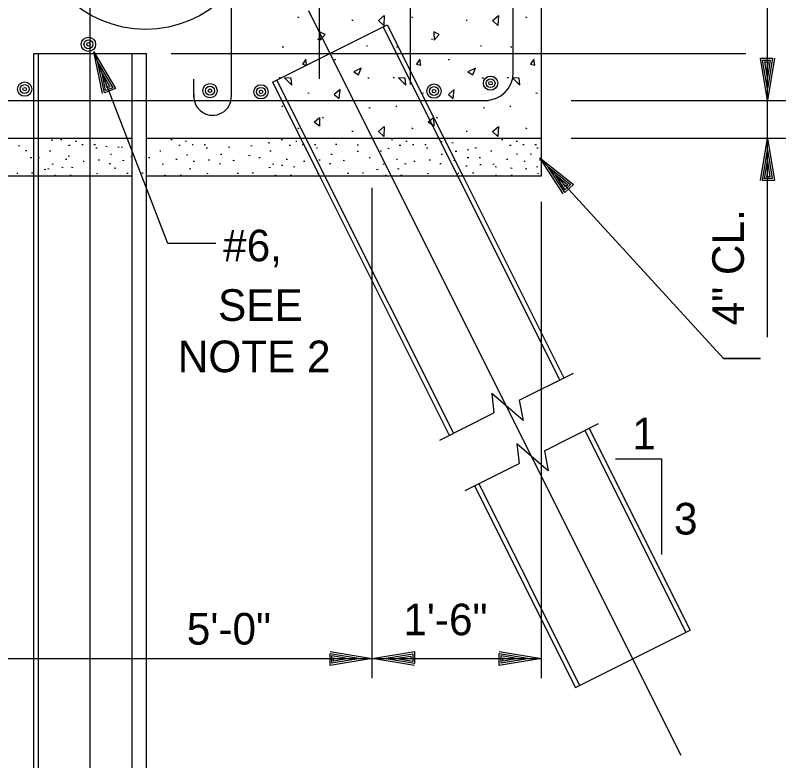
# Model space of a CAD drawing. Extents: x -11983 to -11903, y -13969.5 to -13913.5.
# Drawn here: x -11916.98 to -11910.22, y -13934.76 to -13928.16 of the extents above; entities that cross this region are included whole.
import ezdxf

# ---------------------------------------------------------------- set-up
doc = ezdxf.new("R2010")
doc.units = 0
for name, color, linetype in [('Level 2', 7, 'Continuous'), ('Level 22', 7, 'Continuous'), ('Level 3', 7, 'Continuous'), ('Level 44', 7, 'Continuous'), ('Level 6', 7, 'Continuous')]:
    doc.layers.add(name, color=color, linetype=linetype)

msp = doc.modelspace()

# ---------------------------------------------------------------- linework, layer by layer
at = {"layer": 'Level 2'}
for p, q in [((-11912.3187, -13929.5829), (-11912.3187, -13926.7524)), ((-11914.6994, -13928.7546), (-11913.684, -13928.2466)), ((-11913.7212, -13928.2654), (-11913.0627, -13929.5829)), ((-11913.684, -13928.2466), (-11913.0161, -13929.5829)), ((-11916.8142, -13928.5006), (-11915.8152, -13928.5006)), ((-11916.8142, -13929.5829), (-11916.8142, -13928.5006)), ((-11916.7727, -13936.0221), (-11916.7727, -13928.5006)), ((-11915.944, -13935.9786), (-11915.944, -13928.5006)), ((-11915.8152, -13936.0221), (-11915.8152, -13928.5006)), ((-11914.6994, -13928.7546), (-11914.2855, -13929.5829)), ((-11914.6623, -13928.7358), (-11914.2389, -13929.5829)), ((-11919.811, -13928.9169), (-11913.3132, -13928.9169)), ((-11913.3132, -13928.9169), (-11912.7877, -13928.9169)), ((-11920.3107, -13929.2499), (-11915.944, -13929.2499)), ((-11915.8152, -13929.2499), (-11912.3187, -13929.2499)), ((-11920.3107, -13929.5829), (-11915.944, -13929.5829)), ((-11916.8142, -13936.0221), (-11916.8142, -13929.5829)), ((-11915.8152, -13929.5829), (-11912.3187, -13929.5829)), ((-11914.2854, -13929.5829), (-11913.1356, -13931.8821)), ((-11914.2388, -13929.5829), (-11913.0984, -13931.8635)), ((-11913.0626, -13929.5829), (-11912.1575, -13931.3928)), ((-11913.016, -13929.5829), (-11912.1202, -13931.3741)), ((-11912.516, -13931.5721), (-11912.0362, -13931.3321)), ((-11912.4825, -13931.7499), (-11912.76, -13931.5106)), ((-11912.76, -13931.5106), (-11912.7395, -13931.6839)), ((-11912.516, -13931.5721), (-11912.4825, -13931.7499)), ((-11913.219, -13931.9239), (-11912.7395, -13931.6839)), ((-11912.2927, -13932.0189), (-11911.813, -13931.7789)), ((-11911.9341, -13931.8394), (-11911.0405, -13933.6264)), ((-11911.8969, -13931.8208), (-11911.0033, -13933.6077)), ((-11912.2592, -13932.1966), (-11912.5367, -13931.9574)), ((-11912.5367, -13931.9574), (-11912.5162, -13932.1306)), ((-11912.2927, -13932.0189), (-11912.2592, -13932.1966)), ((-11912.9957, -13932.3706), (-11912.5162, -13932.1306)), ((-11912.9123, -13932.3288), (-11912.0187, -13934.1157)), ((-11912.875, -13932.3102), (-11911.9814, -13934.0971)), ((-11912.0187, -13934.1157), (-11911.0033, -13933.6077))]:
    msp.add_line(p, q, dxfattribs=at)
at = {"layer": 'Level 22'}
for p, q in [((-11915.3972, -13928.8877), (-11915.3972, -13928.7272)), ((-11911.665, -13932.0914), (-11911.2541, -13932.0914)), ((-11911.2541, -13932.9377), (-11911.2541, -13932.0914))]:
    msp.add_line(p, q, dxfattribs=at)
at = {"layer": 'Level 3'}
for p, q in [((-11916.3147, -13930.0624), (-11916.3147, -13928.0259)), ((-11910.3187, -13928.9169), (-11910.3187, -13928.0704)), ((-11914.383, -13928.118), (-11913.8172, -13929.2499)), ((-11916.2833, -13928.4841), (-11916.2833, -13928.4841)), ((-11915.5982, -13928.5006), (-11910.5093, -13928.5006)), ((-11916.2458, -13928.5811), (-11916.2458, -13928.5811)), ((-11910.3187, -13929.3321), (-11910.3187, -13928.7666)), ((-11910.3187, -13928.8129), (-11910.3187, -13928.8129)), ((-11912.0557, -13928.9169), (-11910.0977, -13928.9169)), ((-11910.3187, -13928.9169), (-11910.3187, -13928.9169)), ((-11913.8172, -13929.2499), (-11911.0845, -13934.7146)), ((-11912.0572, -13929.2499), (-11906.994, -13929.2499)), ((-11910.3187, -13931.0129), (-11910.3187, -13929.2499)), ((-11910.3187, -13929.2499), (-11910.3187, -13929.2499)), ((-11910.3187, -13929.3539), (-11910.3187, -13929.3539)), ((-11912.3339, -13929.4257), (-11912.3339, -13929.4257)), ((-11912.2636, -13929.5024), (-11912.2636, -13929.5024)), ((-11913.8172, -13934.0336), (-11913.8172, -13929.6907)), ((-11912.3187, -13934.0336), (-11912.3187, -13929.8129)), ((-11916.3147, -13936.7181), (-11916.3147, -13930.0624)), ((-11910.7062, -13931.2009), (-11910.3797, -13931.2009)), ((-11918.8122, -13933.8594), (-11913.8172, -13933.8594)), ((-11913.9212, -13933.8594), (-11913.9212, -13933.8594)), ((-11913.8172, -13933.8594), (-11912.3187, -13933.8594)), ((-11913.8172, -13933.8594), (-11913.8172, -13933.8594)), ((-11913.8172, -13933.8594), (-11913.8172, -13933.8594)), ((-11913.7132, -13933.8594), (-11913.7132, -13933.8594)), ((-11912.4227, -13933.8594), (-11912.4227, -13933.8594)), ((-11912.3187, -13933.8594), (-11912.3187, -13933.8594))]:
    msp.add_line(p, q, dxfattribs=at)
for points in [[(-11915.2026, -13930.184), (-11915.626, -13930.184), (-11916.2833, -13928.4841)], [(-11916.2063, -13928.8553), (-11916.2833, -13928.4841), (-11916.0906, -13928.8106), (-11916.1895, -13928.8488), (-11916.2458, -13928.5811), (-11916.115, -13928.8029), (-11916.1785, -13928.8274), (-11916.2098, -13928.6744), (-11916.1395, -13928.7952), (-11916.1656, -13928.8053), (-11916.1723, -13928.7714)], [(-11910.2567, -13928.5429), (-11910.3187, -13928.9169), (-11910.3807, -13928.5429), (-11910.2747, -13928.5429), (-11910.3187, -13928.8129), (-11910.3607, -13928.5589), (-11910.2927, -13928.5589), (-11910.3187, -13928.7129), (-11910.3407, -13928.5749), (-11910.3127, -13928.5749), (-11910.3187, -13928.6089)], [(-11910.3807, -13929.6239), (-11910.3187, -13929.2499), (-11910.2567, -13929.6239), (-11910.3627, -13929.6239), (-11910.3187, -13929.3539), (-11910.2767, -13929.6079), (-11910.3447, -13929.6079), (-11910.3187, -13929.4539), (-11910.2967, -13929.5919), (-11910.3247, -13929.5919), (-11910.3187, -13929.5579)], [(-11910.3797, -13931.2009), (-11910.7062, -13931.2009), (-11912.3339, -13929.4257)], [(-11912.1268, -13929.7433), (-11912.3339, -13929.4257), (-11912.0354, -13929.6595), (-11912.1136, -13929.7311), (-11912.2636, -13929.5024), (-11912.061, -13929.6612), (-11912.1111, -13929.7071), (-11912.196, -13929.5761), (-11912.0865, -13929.6629), (-11912.1072, -13929.6818), (-11912.1257, -13929.6527)], [(-11914.1912, -13933.7974), (-11913.8172, -13933.8594), (-11914.1912, -13933.9214), (-11914.1912, -13933.8154), (-11913.9212, -13933.8594), (-11914.1752, -13933.9014), (-11914.1752, -13933.8334), (-11914.0212, -13933.8594), (-11914.1592, -13933.8814), (-11914.1592, -13933.8534), (-11914.1252, -13933.8594)], [(-11913.4432, -13933.9214), (-11913.8172, -13933.8594), (-11913.4432, -13933.7974), (-11913.4432, -13933.9034), (-11913.7132, -13933.8594), (-11913.4592, -13933.8174), (-11913.4592, -13933.8854), (-11913.6132, -13933.8594), (-11913.4752, -13933.8374), (-11913.4752, -13933.8654), (-11913.5092, -13933.8594)], [(-11912.6927, -13933.7974), (-11912.3187, -13933.8594), (-11912.6927, -13933.9214), (-11912.6927, -13933.8154), (-11912.4227, -13933.8594), (-11912.6767, -13933.9014), (-11912.6767, -13933.8334), (-11912.5227, -13933.8594), (-11912.6607, -13933.8814), (-11912.6607, -13933.8534), (-11912.6267, -13933.8594)]]:
    msp.add_lwpolyline(points, dxfattribs=at)
msp.add_circle((-11915.8239, -13927.2866), 1, dxfattribs=at)
msp.add_arc((-11912.8185, -13928.6669), 0.25, 270, 0, dxfattribs=at)
at = {"layer": 'Level 44'}
for p, q in [((-11914.4655, -13928.183), (-11914.4763, -13928.178)), ((-11913.9858, -13928.207), (-11913.9968, -13928.208)), ((-11913.4555, -13928.183), (-11913.4663, -13928.178)), ((-11912.9758, -13928.207), (-11912.9868, -13928.208)), ((-11912.4455, -13928.183), (-11912.4563, -13928.178)), ((-11914.2928, -13928.3772), (-11914.3028, -13928.3765)), ((-11913.8595, -13928.4357), (-11913.8695, -13928.434)), ((-11913.2828, -13928.3772), (-11913.2928, -13928.3765)), ((-11912.8495, -13928.4357), (-11912.8595, -13928.434)), ((-11914.6005, -13928.4442), (-11914.614, -13928.4442)), ((-11913.5905, -13928.4442), (-11913.604, -13928.4442)), ((-11912.5805, -13928.4442), (-11912.594, -13928.4442)), ((-11914.1425, -13928.5535), (-11914.1545, -13928.5595)), ((-11913.1325, -13928.5535), (-11913.1445, -13928.5595)), ((-11914.6295, -13928.7147), (-11914.6423, -13928.7147)), ((-11913.8435, -13928.7195), (-11913.857, -13928.7195)), ((-11913.6195, -13928.7147), (-11913.6323, -13928.7147)), ((-11912.8335, -13928.7195), (-11912.847, -13928.7195)), ((-11912.6095, -13928.7147), (-11912.6223, -13928.7147)), ((-11914.375, -13928.8545), (-11914.388, -13928.8522)), ((-11913.365, -13928.8545), (-11913.378, -13928.8522)), ((-11912.355, -13928.8545), (-11912.368, -13928.8522)), ((-11914.6098, -13928.9677), (-11914.6195, -13928.9715)), ((-11913.5998, -13928.9677), (-11913.6095, -13928.9715)), ((-11912.5898, -13928.9677), (-11912.5995, -13928.9715)), ((-11913.8328, -13928.9812), (-11913.8463, -13928.985)), ((-11912.8228, -13928.9812), (-11912.8363, -13928.985)), ((-11914.2478, -13929.0737), (-11914.259, -13929.067)), ((-11913.2378, -13929.0737), (-11913.249, -13929.067)), ((-11914.4655, -13929.1667), (-11914.4763, -13929.1617)), ((-11913.4555, -13929.1667), (-11913.4663, -13929.1617)), ((-11912.4455, -13929.1667), (-11912.4563, -13929.1617)), ((-11913.9858, -13929.1907), (-11913.9968, -13929.1917)), ((-11912.9758, -13929.1907), (-11912.9868, -13929.1917)), ((-11916.9377, -13929.3198), (-11916.9507, -13929.3178)), ((-11916.6466, -13929.2702), (-11916.6596, -13929.2682)), ((-11916.5655, -13929.2637), (-11916.5765, -13929.2647)), ((-11916.493, -13929.315), (-11916.5065, -13929.315)), ((-11916.437, -13929.2787), (-11916.448, -13929.2795)), ((-11916.3783, -13929.3095), (-11916.3895, -13929.3102)), ((-11916.2693, -13929.3095), (-11916.2818, -13929.3095)), ((-11915.5893, -13929.2637), (-11915.6003, -13929.2647)), ((-11915.5168, -13929.315), (-11915.5303, -13929.315)), ((-11915.4608, -13929.2787), (-11915.4718, -13929.2795)), ((-11915.402, -13929.3095), (-11915.4133, -13929.3102)), ((-11915.293, -13929.3095), (-11915.3055, -13929.3095)), ((-11914.8802, -13929.3198), (-11914.8932, -13929.3178)), ((-11914.7253, -13929.295), (-11914.7383, -13929.293)), ((-11914.613, -13929.2637), (-11914.624, -13929.2647)), ((-11914.5405, -13929.315), (-11914.554, -13929.315)), ((-11914.4845, -13929.2787), (-11914.4955, -13929.2795)), ((-11914.4258, -13929.3095), (-11914.437, -13929.3102)), ((-11914.3168, -13929.3095), (-11914.3293, -13929.3095)), ((-11914.1308, -13929.3074), (-11914.1438, -13929.3054)), ((-11913.9389, -13929.3136), (-11913.9519, -13929.3116)), ((-11913.6368, -13929.2637), (-11913.6478, -13929.2647)), ((-11913.5643, -13929.315), (-11913.5778, -13929.315)), ((-11913.5083, -13929.2787), (-11913.5193, -13929.2795)), ((-11913.4495, -13929.3095), (-11913.4608, -13929.3102)), ((-11913.3405, -13929.3095), (-11913.353, -13929.3095)), ((-11913.1988, -13929.2826), (-11913.2118, -13929.2806)), ((-11913.0997, -13929.295), (-11913.1127, -13929.293)), ((-11912.6605, -13929.2637), (-11912.6715, -13929.2647)), ((-11912.588, -13929.315), (-11912.6015, -13929.315)), ((-11912.532, -13929.2787), (-11912.543, -13929.2795)), ((-11912.4733, -13929.3095), (-11912.4845, -13929.3102)), ((-11912.3643, -13929.3095), (-11912.3768, -13929.3095)), ((-11916.8758, -13929.3632), (-11916.8888, -13929.3612)), ((-11916.6645, -13929.3642), (-11916.6755, -13929.3652)), ((-11916.2538, -13929.3387), (-11916.2648, -13929.3395)), ((-11916.1636, -13929.326), (-11916.1766, -13929.324)), ((-11916.0583, -13929.3322), (-11916.0713, -13929.3302)), ((-11916.0274, -13929.3322), (-11916.0404, -13929.3302)), ((-11915.6883, -13929.3642), (-11915.6993, -13929.3652)), ((-11915.2775, -13929.3387), (-11915.2885, -13929.3395)), ((-11915.0783, -13929.3322), (-11915.0913, -13929.3302)), ((-11914.712, -13929.3642), (-11914.723, -13929.3652)), ((-11914.3013, -13929.3387), (-11914.3123, -13929.3395)), ((-11913.9389, -13929.3694), (-11913.9519, -13929.3674)), ((-11913.7358, -13929.3642), (-11913.7468, -13929.3652)), ((-11913.6664, -13929.3446), (-11913.6794, -13929.3426)), ((-11913.325, -13929.3387), (-11913.336, -13929.3395)), ((-11913.0688, -13929.3694), (-11913.0818, -13929.3674)), ((-11912.9635, -13929.357), (-11912.9765, -13929.355)), ((-11912.8954, -13929.3384), (-11912.9084, -13929.3364)), ((-11912.7595, -13929.3642), (-11912.7705, -13929.3652)), ((-11912.3488, -13929.3387), (-11912.3598, -13929.3395)), ((-11916.8324, -13929.4252), (-11916.8454, -13929.4232)), ((-11916.7638, -13929.423), (-11916.7748, -13929.424)), ((-11916.5215, -13929.4377), (-11916.5325, -13929.4385)), ((-11916.498, -13929.4128), (-11916.511, -13929.4108)), ((-11916.2318, -13929.445), (-11916.2428, -13929.446)), ((-11916.1253, -13929.3937), (-11916.1363, -13929.3947)), ((-11916.0145, -13929.45), (-11916.0275, -13929.448)), ((-11915.9407, -13929.419), (-11915.9537, -13929.417)), ((-11915.7875, -13929.423), (-11915.7985, -13929.424)), ((-11915.5453, -13929.4377), (-11915.5563, -13929.4385)), ((-11915.4499, -13929.4004), (-11915.4629, -13929.3984)), ((-11915.2555, -13929.445), (-11915.2665, -13929.446)), ((-11915.149, -13929.3937), (-11915.16, -13929.3947)), ((-11915.0383, -13929.45), (-11915.0513, -13929.448)), ((-11914.8987, -13929.4066), (-11914.9117, -13929.4046)), ((-11914.8113, -13929.423), (-11914.8223, -13929.424)), ((-11914.569, -13929.4377), (-11914.58, -13929.4385)), ((-11914.2793, -13929.445), (-11914.2903, -13929.446)), ((-11914.1728, -13929.3937), (-11914.1838, -13929.3947)), ((-11914.062, -13929.45), (-11914.075, -13929.448)), ((-11913.835, -13929.423), (-11913.846, -13929.424)), ((-11913.5928, -13929.4377), (-11913.6038, -13929.4385)), ((-11913.303, -13929.445), (-11913.314, -13929.446)), ((-11913.1965, -13929.3937), (-11913.2075, -13929.3947)), ((-11913.0858, -13929.45), (-11913.0988, -13929.448)), ((-11912.9635, -13929.4252), (-11912.9765, -13929.4232)), ((-11912.8588, -13929.423), (-11912.8698, -13929.424)), ((-11912.6165, -13929.4377), (-11912.6275, -13929.4385)), ((-11912.53, -13929.3942), (-11912.543, -13929.3922)), ((-11912.4061, -13929.3942), (-11912.4191, -13929.3922)), ((-11912.3268, -13929.445), (-11912.3378, -13929.446)), ((-11916.6428, -13929.4817), (-11916.6538, -13929.4827)), ((-11916.5538, -13929.5119), (-11916.5668, -13929.5099)), ((-11916.4671, -13929.5119), (-11916.4801, -13929.5099)), ((-11916.3673, -13929.456), (-11916.3783, -13929.457)), ((-11916.1363, -13929.4782), (-11916.1473, -13929.479)), ((-11916.0893, -13929.5181), (-11916.1023, -13929.5161)), ((-11915.6665, -13929.4817), (-11915.6775, -13929.4827)), ((-11915.391, -13929.456), (-11915.402, -13929.457)), ((-11915.16, -13929.4782), (-11915.171, -13929.479)), ((-11914.7191, -13929.5119), (-11914.7321, -13929.5099)), ((-11914.6903, -13929.4817), (-11914.7013, -13929.4827)), ((-11914.6077, -13929.4934), (-11914.6207, -13929.4914)), ((-11914.5024, -13929.5058), (-11914.5154, -13929.5038)), ((-11914.4148, -13929.456), (-11914.4258, -13929.457)), ((-11914.1838, -13929.4782), (-11914.1948, -13929.479)), ((-11913.714, -13929.4817), (-11913.725, -13929.4827)), ((-11913.5177, -13929.481), (-11913.5307, -13929.479)), ((-11913.4385, -13929.456), (-11913.4495, -13929.457)), ((-11913.2075, -13929.4782), (-11913.2185, -13929.479)), ((-11912.9759, -13929.4996), (-11912.9889, -13929.4976)), ((-11912.852, -13929.4872), (-11912.865, -13929.4852)), ((-11912.7378, -13929.4817), (-11912.7488, -13929.4827)), ((-11912.7158, -13929.5058), (-11912.7288, -13929.5038)), ((-11912.5795, -13929.5181), (-11912.5925, -13929.5161)), ((-11912.4623, -13929.456), (-11912.4733, -13929.457)), ((-11912.3504, -13929.5058), (-11912.3634, -13929.5038)), ((-11916.9548, -13929.5625), (-11916.9658, -13929.5635)), ((-11916.8225, -13929.559), (-11916.8335, -13929.5597)), ((-11916.7086, -13929.5305), (-11916.7216, -13929.5285)), ((-11916.6776, -13929.5243), (-11916.6906, -13929.5223)), ((-11916.6208, -13929.5807), (-11916.6318, -13929.5817)), ((-11916.4823, -13929.577), (-11916.4958, -13929.5807)), ((-11916.2495, -13929.5635), (-11916.259, -13929.5672)), ((-11915.9785, -13929.5625), (-11915.9895, -13929.5635)), ((-11915.8463, -13929.559), (-11915.8573, -13929.5597)), ((-11915.6445, -13929.5807), (-11915.6555, -13929.5817)), ((-11915.506, -13929.577), (-11915.5195, -13929.5807)), ((-11915.4251, -13929.5243), (-11915.4381, -13929.5223)), ((-11915.2733, -13929.5635), (-11915.2828, -13929.5672)), ((-11915.0023, -13929.5625), (-11915.0133, -13929.5635)), ((-11914.87, -13929.559), (-11914.881, -13929.5597)), ((-11914.6683, -13929.5807), (-11914.6793, -13929.5817)), ((-11914.5298, -13929.577), (-11914.5433, -13929.5807)), ((-11914.297, -13929.5635), (-11914.3065, -13929.5672)), ((-11914.026, -13929.5625), (-11914.037, -13929.5635)), ((-11913.8938, -13929.559), (-11913.9048, -13929.5597)), ((-11913.7654, -13929.5305), (-11913.7784, -13929.5285)), ((-11913.692, -13929.5807), (-11913.703, -13929.5817)), ((-11913.5797, -13929.5243), (-11913.5927, -13929.5223)), ((-11913.5535, -13929.577), (-11913.567, -13929.5807)), ((-11913.3208, -13929.5635), (-11913.3303, -13929.5672)), ((-11913.0498, -13929.5625), (-11913.0608, -13929.5635)), ((-11912.9175, -13929.559), (-11912.9285, -13929.5597)), ((-11912.7158, -13929.5807), (-11912.7268, -13929.5817)), ((-11912.5773, -13929.577), (-11912.5908, -13929.5807)), ((-11912.4495, -13929.5243), (-11912.4625, -13929.5223)), ((-11912.3445, -13929.5635), (-11912.354, -13929.5672))]:
    msp.add_line(p, q, dxfattribs=at)
for points in [[(-11913.7155, -13928.251), (-11913.7618, -13928.2082), (-11913.7105, -13928.1625)], [(-11912.7055, -13928.251), (-11912.7518, -13928.2082), (-11912.7005, -13928.1625)], [(-11914.2783, -13928.3807), (-11914.2355, -13928.3327), (-11914.2833, -13928.3072)], [(-11913.2683, -13928.3807), (-11913.2255, -13928.3327), (-11913.2733, -13928.3072)], [(-11914.3985, -13928.6042), (-11914.4055, -13928.5495), (-11914.4363, -13928.5952)], [(-11913.3885, -13928.6042), (-11913.3955, -13928.5495), (-11913.4263, -13928.5952)], [(-11912.3785, -13928.6042), (-11912.3855, -13928.5495), (-11912.4163, -13928.5952)], [(-11913.938, -13928.6902), (-11913.9143, -13928.629), (-11913.9805, -13928.6612)], [(-11912.928, -13928.6902), (-11912.9043, -13928.629), (-11912.9705, -13928.6612)], [(-11914.5358, -13928.718), (-11914.5958, -13928.7147), (-11914.5308, -13928.7812)], [(-11913.5258, -13928.718), (-11913.5858, -13928.7147), (-11913.5208, -13928.7812)], [(-11912.5158, -13928.718), (-11912.5758, -13928.7147), (-11912.5108, -13928.7812)], [(-11914.102, -13928.8185), (-11914.1533, -13928.8632), (-11914.1108, -13928.899)], [(-11913.092, -13928.8185), (-11913.1433, -13928.8632), (-11913.1008, -13928.899)], [(-11914.2833, -13929.1445), (-11914.3313, -13929.1082), (-11914.2853, -13929.0675)], [(-11913.2733, -13929.1445), (-11913.3213, -13929.1082), (-11913.2753, -13929.0675)], [(-11913.7155, -13929.2347), (-11913.7618, -13929.192), (-11913.7105, -13929.1462)], [(-11912.7055, -13929.2347), (-11912.7518, -13929.192), (-11912.7005, -13929.1462)]]:
    msp.add_lwpolyline(points, close=True, dxfattribs=at)
at = {"layer": 'Level 6'}
for p, q in [((-11915.0645, -13928.8739), (-11915.0645, -13919.9188)), ((-11914.288, -13919.9188), (-11914.288, -13928.7258)), ((-11913.4808, -13919.9188), (-11913.4808, -13928.7749)), ((-11912.5685, -13928.6669), (-11912.5685, -13927.1674))]:
    msp.add_line(p, q, dxfattribs=at)
for centre, radius in [((-11916.3302, -13928.4191), 0.0633), ((-11916.3302, -13928.4191), 0.0396), ((-11916.3302, -13928.4191), 0.0158), ((-11912.77, -13928.7631), 0.0633), ((-11916.8947, -13928.8159), 0.0633), ((-11916.8947, -13928.8159), 0.0396), ((-11915.2542, -13928.8297), 0.0633), ((-11914.8027, -13928.8397), 0.0633), ((-11913.2708, -13928.8335), 0.0633), ((-11912.77, -13928.7631), 0.0396), ((-11912.77, -13928.7631), 0.0158), ((-11916.8947, -13928.8159), 0.0158), ((-11915.2542, -13928.8297), 0.0396), ((-11915.2542, -13928.8297), 0.0158), ((-11914.8027, -13928.8397), 0.0396), ((-11914.8027, -13928.8397), 0.0158), ((-11913.2708, -13928.8335), 0.0396), ((-11913.2708, -13928.8335), 0.0158)]:
    msp.add_circle(centre, radius, dxfattribs=at)
msp.add_arc((-11915.2309, -13928.8808), 0.1665, 174.25234, 2.36701, dxfattribs=at)

# ---------------------------------------------------------------- texts
at = {"layer": 'Level 3'}
msp.add_text('4" CL.', height=0.28, rotation=90, dxfattribs=at).set_placement((-11910.5268, -13930.9079))
for s, p in [('#6,', (-11915.1375, -13930.3409)), ('SEE', (-11915.1827, -13930.8684)), ('NOTE 2', (-11915.539, -13931.3231)), ('1', (-11911.5142, -13932.0062)), ('3', (-11911.1455, -13932.7607)), ('1\'-6"', (-11913.5424, -13933.653)), ('5\'-0"', (-11915.4593, -13933.7356))]:
    msp.add_text(s, height=0.28, dxfattribs=at).set_placement(p)

doc.saveas('drawing.dxf')
